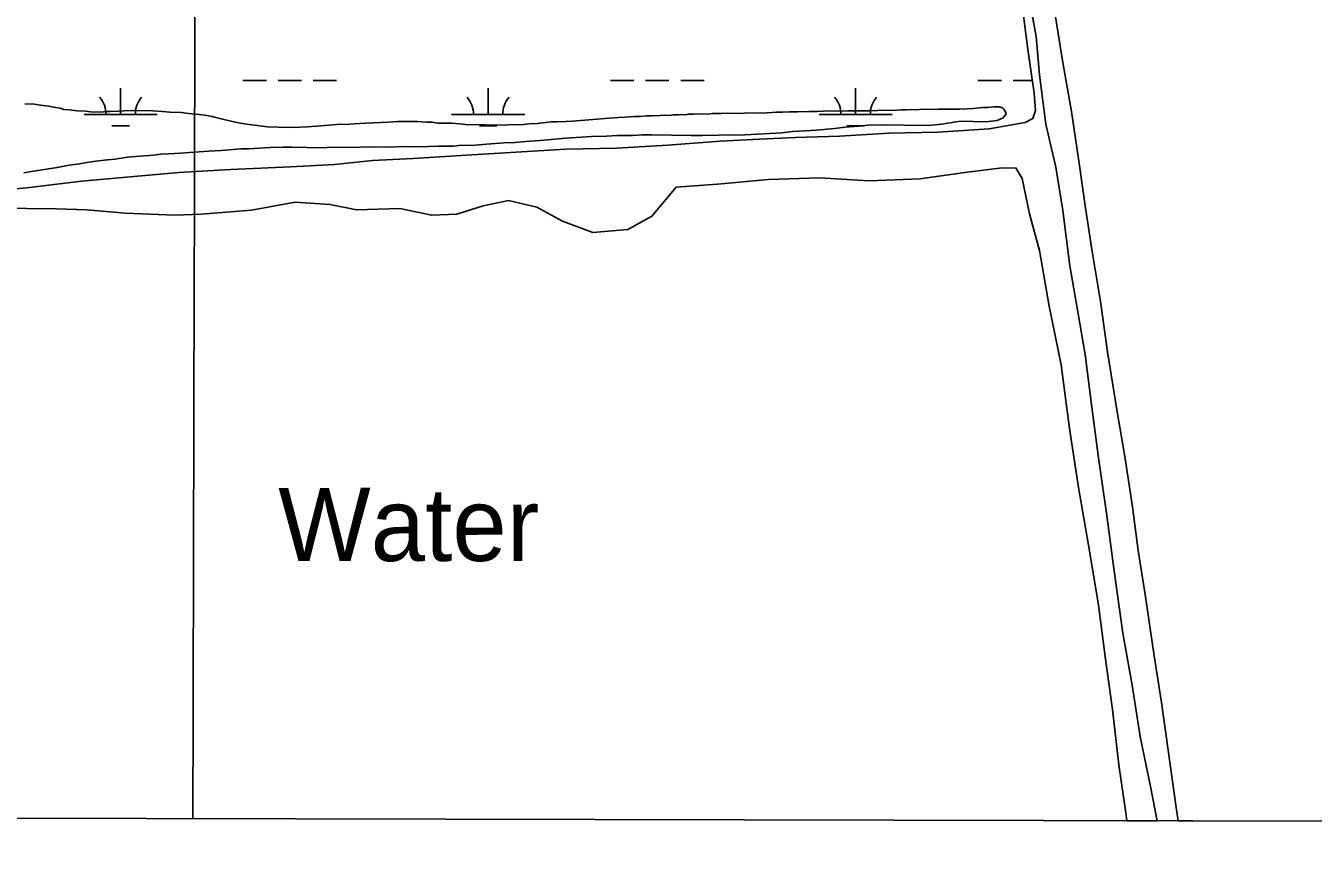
# Model space of a CAD drawing. Extents: x 3177185 to 3215018, y 812988 to 838321.
# Drawn here: x 3191596 to 3193354, y 818326 to 819458 of the extents above; entities that cross this region are included whole.
import ezdxf

# ---------------------------------------------------------------- set-up
doc = ezdxf.new("R2010")
doc.units = 0
for name, color, linetype in [('V-GRID-FRAM', 7, 'Continuous'), ('V-GRID-MAJR', 7, 'Continuous'), ('V-RIVR-IDEN', 7, 'Continuous'), ('V-SITE-VEGE', 7, 'Continuous'), ('V-TOPO-SHOR', 7, 'Continuous'), ('V-WETL-SWMP', 7, 'Continuous')]:
    doc.layers.add(name, color=color, linetype=linetype)

msp = doc.modelspace()

# ---------------------------------------------------------------- linework, layer by layer
at = {"layer": 'V-GRID-FRAM'}
msp.add_lwpolyline([(3181402.4, 836586.1), (3212801.6, 836513), (3212767.2, 818326.1), (3181352.2, 818399.3), (3181402.4, 836586.1)], dxfattribs=at)
at = {"layer": 'V-GRID-MAJR'}
msp.add_spline([(3191823.8, 818374.9), (3191838.8, 824434.1), (3191853.8, 830496.4), (3191868.8, 836558.7), (3191868.8, 836561.7)], degree=3, dxfattribs=at)
at = {"layer": 'V-SITE-VEGE'}
for p, q in [((3192964.9, 819500.9), (3192975.4, 819442.8)), ((3193011.9, 819407.5), (3193001.5, 819472.5)), ((3192975.4, 819442.8), (3192980.1, 819390.4)), ((3193024, 819340.5), (3193011.9, 819407.5)), ((3192980.1, 819390.4), (3192988.9, 819323.3)), ((3191607.5, 819350.5), (3191594.3, 819350.8)), ((3191615.3, 819349), (3191607.5, 819350.5)), ((3191627.1, 819347.9), (3191615.3, 819349)), ((3191633.5, 819346.4), (3191627.1, 819347.9)), ((3191642.6, 819344.9), (3191633.5, 819346.4)), ((3191647.6, 819343.4), (3191642.6, 819344.9)), ((3192880.4, 819344.4), (3192870.8, 819343.7)), ((3192889.5, 819344.7), (3192880.4, 819344.4)), ((3192902.3, 819345.9), (3192889.5, 819344.7)), ((3192909.6, 819346.2), (3192902.3, 819345.9)), ((3192917.9, 819347), (3192909.6, 819346.2)), ((3192925.2, 819346.8), (3192917.9, 819347)), ((3192929.7, 819345.4), (3192925.2, 819346.8)), ((3192931.5, 819343.5), (3192929.7, 819345.4)), ((3191654.9, 819342.9), (3191647.6, 819343.4)), ((3191665.8, 819341.3), (3191654.9, 819342.9)), ((3191677.2, 819341.1), (3191665.8, 819341.3)), ((3191684.5, 819340), (3191677.2, 819341.1)), ((3191698.6, 819339.8), (3191684.5, 819340)), ((3191705, 819340.6), (3191698.6, 819339.8)), ((3191711.4, 819340.5), (3191705, 819340.6)), ((3191721.9, 819340.8), (3191711.4, 819340.5)), ((3191729.7, 819341.5), (3191721.9, 819340.8)), ((3191740.7, 819341.8), (3191729.7, 819341.5)), ((3191769, 819341.3), (3191740.7, 819341.8)), ((3191782.6, 819340.6), (3191769, 819341.3)), ((3191792.2, 819339.5), (3191782.6, 819340.6)), ((3191808.2, 819339.2), (3191792.2, 819339.5)), ((3191817.7, 819337.7), (3191808.2, 819339.2)), ((3191832.3, 819336.5), (3191817.7, 819337.7)), ((3191840, 819335.5), (3191832.3, 819336.5)), ((3191850.1, 819333.5), (3191840, 819335.5)), ((3191853.2, 819333), (3191850.1, 819333.5)), ((3191864.1, 819330), (3191853.2, 819333)), ((3191871.9, 819328.1), (3191864.1, 819330)), ((3191886, 819325.1), (3191871.9, 819328.1)), ((3192112.8, 819327), (3192103.7, 819326.7)), ((3192130.6, 819326.7), (3192112.8, 819327)), ((3192342.4, 819327.5), (3192333.3, 819326.7)), ((3192392.2, 819331.2), (3192342.4, 819327.5)), ((3192405, 819332.3), (3192392.2, 819331.2)), ((3192414.2, 819332.6), (3192405, 819332.3)), ((3192427, 819333.8), (3192414.2, 819332.6)), ((3192434.7, 819333.6), (3192427, 819333.8)), ((3192443.4, 819334.8), (3192434.7, 819333.6)), ((3192451.2, 819334.7), (3192443.4, 819334.8)), ((3192462.1, 819335), (3192451.2, 819334.7)), ((3192467.6, 819335.3), (3192462.1, 819335)), ((3192475.4, 819335.2), (3192467.6, 819335.3)), ((3192480, 819336), (3192475.4, 819335.2)), ((3192487.3, 819335.9), (3192480, 819336)), ((3192491.8, 819336.3), (3192487.3, 819335.9)), ((3192496.9, 819336.2), (3192491.8, 819336.3)), ((3192500.1, 819337), (3192496.9, 819336.2)), ((3192507.4, 819336.9), (3192500.1, 819337)), ((3192513.8, 819337.2), (3192507.4, 819336.9)), ((3192527.4, 819337), (3192513.8, 819337.2)), ((3192532.9, 819337.8), (3192527.4, 819337)), ((3192540.7, 819337.7), (3192532.9, 819337.8)), ((3192545.3, 819338), (3192540.7, 819337.7)), ((3192553.5, 819338.4), (3192545.3, 819338)), ((3192573.6, 819338), (3192553.5, 819338.4)), ((3192580.9, 819338.8), (3192573.6, 819338)), ((3192601.4, 819338.4), (3192580.9, 819338.8)), ((3192621.1, 819339.4), (3192601.4, 819338.4)), ((3192629.3, 819339.8), (3192621.1, 819339.4)), ((3192638.9, 819340), (3192629.3, 819339.8)), ((3192649.4, 819339.9), (3192638.9, 819340)), ((3192665.3, 819340.5), (3192649.4, 819339.9)), ((3192676.3, 819340.7), (3192665.3, 819340.5)), ((3192692.7, 819341.4), (3192676.3, 819340.7)), ((3192703.7, 819341.2), (3192692.7, 819341.4)), ((3192719.2, 819341.4), (3192703.7, 819341.2)), ((3192730.2, 819341.6), (3192719.2, 819341.4)), ((3192747.5, 819341.3), (3192730.2, 819341.6)), ((3192758.9, 819342), (3192747.5, 819341.3)), ((3192773.1, 819342.2), (3192758.9, 819342)), ((3192780.4, 819342.1), (3192773.1, 819342.2)), ((3192790.9, 819342.8), (3192780.4, 819342.1)), ((3192797.8, 819342.7), (3192790.9, 819342.8)), ((3192804.1, 819343.1), (3192797.8, 819342.7)), ((3192811.4, 819342.9), (3192804.1, 819343.1)), ((3192821.5, 819343.7), (3192811.4, 819342.9)), ((3192836.6, 819343.4), (3192821.5, 819343.7)), ((3192841.6, 819343.8), (3192836.6, 819343.4)), ((3192853.9, 819343.5), (3192841.6, 819343.8)), ((3192870.8, 819343.7), (3192853.9, 819343.5)), ((3192866.4, 819326.4), (3192872.3, 819327.2)), ((3192872.3, 819327.2), (3192906.6, 819326.6)), ((3192906.6, 819326.6), (3192922.1, 819328.2)), ((3192922.1, 819328.2), (3192930.4, 819331.7)), ((3192930.4, 819331.7), (3192934.6, 819337.5)), ((3192933.7, 819340.3), (3192931.5, 819343.5)), ((3192934.6, 819337.5), (3192933.7, 819340.3)), ((3193034.9, 819267), (3193024, 819340.5)), ((3191896.9, 819323.1), (3191886, 819325.1)), ((3191915.1, 819320.9), (3191896.9, 819323.1)), ((3191926, 819319.8), (3191915.1, 819320.9)), ((3191940.2, 819319.1), (3191926, 819319.8)), ((3191957.5, 819318.8), (3191940.2, 819319.1)), ((3191969.8, 819319), (3191957.5, 819318.8)), ((3191979.4, 819319.8), (3191969.8, 819319)), ((3191993.1, 819320.4), (3191979.4, 819319.8)), ((3192015.1, 819322.3), (3191993.1, 819320.4)), ((3192025.6, 819323.1), (3192015.1, 819322.3)), ((3192030.6, 819323), (3192025.6, 819323.1)), ((3192052.1, 819324), (3192030.6, 819323)), ((3192059.9, 819324.7), (3192052.1, 819324)), ((3192090.9, 819326), (3192059.9, 819324.7)), ((3192103.7, 819326.7), (3192090.9, 819326)), ((3192142.5, 819326), (3192130.6, 819326.7)), ((3192150.7, 819325.9), (3192142.5, 819326)), ((3192158.4, 819324.8), (3192150.7, 819325.9)), ((3192177.6, 819324.5), (3192158.4, 819324.8)), ((3192188.1, 819323.8), (3192177.6, 819324.5)), ((3192196.3, 819322.8), (3192188.1, 819323.8)), ((3192250.1, 819321.8), (3192196.3, 819322.8)), ((3192260.2, 819322.6), (3192250.1, 819321.8)), ((3192267.9, 819322.4), (3192260.2, 819322.6)), ((3192275.7, 819322.7), (3192267.9, 819322.4)), ((3192283, 819323.5), (3192275.7, 819322.7)), ((3192294.4, 819324.2), (3192283, 819323.5)), ((3192313.2, 819326.2), (3192294.4, 819324.2)), ((3192321, 819326.5), (3192313.2, 819326.2)), ((3192333.3, 819326.7), (3192321, 819326.5)), ((3192569.4, 819308.4), (3192628.3, 819311.5)), ((3192628.3, 819311.5), (3192643, 819313)), ((3192643, 819313), (3192667.6, 819314.4)), ((3192667.6, 819314.4), (3192675.4, 819315.2)), ((3192675.4, 819315.2), (3192700.1, 819317.1)), ((3192700.1, 819317.1), (3192714.7, 819319.1)), ((3192714.7, 819319.1), (3192733.5, 819320.6)), ((3192733.5, 819320.6), (3192745.8, 819321.7)), ((3192745.8, 819321.7), (3192762.7, 819322.3)), ((3192762.7, 819322.3), (3192827.9, 819321.2)), ((3192827.9, 819321.2), (3192846.7, 819323.1)), ((3192846.7, 819323.1), (3192866.4, 819326.4)), ((3192988.9, 819323.3), (3193002.4, 819264.3)), ((3191947, 819291.6), (3191958.4, 819291.8)), ((3191958.4, 819291.8), (3192000.4, 819291.1)), ((3192000.4, 819291.1), (3192014.1, 819291.8)), ((3192014.1, 819291.8), (3192034.2, 819291.4)), ((3192034.2, 819291.4), (3192071.1, 819292.1)), ((3192071.1, 819292.1), (3192092.1, 819291.8)), ((3192092.1, 819291.8), (3192112.2, 819292.8)), ((3192112.2, 819292.8), (3192125.5, 819292.5)), ((3192125.5, 819292.5), (3192145.5, 819292.6)), ((3192145.5, 819292.6), (3192159.3, 819293.3)), ((3192159.3, 819293.3), (3192180.2, 819293.4)), ((3192180.2, 819293.4), (3192187.1, 819294.2)), ((3192187.1, 819294.2), (3192209.5, 819294.7)), ((3192209.5, 819294.7), (3192225, 819295.8)), ((3192225, 819295.8), (3192248.8, 819297.7)), ((3192248.8, 819297.7), (3192263.4, 819298.3)), ((3192263.4, 819298.3), (3192284.4, 819300.2)), ((3192284.4, 819300.2), (3192298.1, 819300.9)), ((3192298.1, 819300.9), (3192332.9, 819303.9)), ((3192332.9, 819303.9), (3192354.4, 819305.4)), ((3192354.4, 819305.4), (3192368.1, 819306.5)), ((3192368.1, 819306.5), (3192388.6, 819307)), ((3192388.6, 819307), (3192402.8, 819307.7)), ((3192402.8, 819307.7), (3192424.2, 819307.8)), ((3192424.2, 819307.8), (3192437.5, 819308.5)), ((3192437.5, 819308.5), (3192450.7, 819308.7)), ((3192450.7, 819308.7), (3192504.6, 819307.7)), ((3192504.6, 819307.7), (3192519.6, 819307.9)), ((3192519.6, 819307.9), (3192542, 819308.4)), ((3192542, 819308.4), (3192556.6, 819308.6)), ((3192556.6, 819308.6), (3192569.4, 819308.4)), ((3191691.5, 819272.8), (3191707.1, 819274.4)), ((3191707.1, 819274.4), (3191717.6, 819275.6)), ((3191717.6, 819275.6), (3191734.5, 819278)), ((3191734.5, 819278), (3191745.5, 819279.2)), ((3191745.5, 819279.2), (3191770.6, 819281)), ((3191770.6, 819281), (3191780.2, 819282.2)), ((3191780.2, 819282.2), (3191790.7, 819282.9)), ((3191790.7, 819282.9), (3191807.6, 819283.6)), ((3191807.6, 819283.6), (3191819.1, 819284.7)), ((3191819.1, 819284.7), (3191845.6, 819286.5)), ((3191845.6, 819286.5), (3191862.5, 819287.1)), ((3191862.5, 819287.1), (3191873.4, 819288.3)), ((3191873.4, 819288.3), (3191889.4, 819289.4)), ((3191889.4, 819289.4), (3191900.4, 819289.7)), ((3191900.4, 819289.7), (3191929.6, 819291.4)), ((3191929.6, 819291.4), (3191947, 819291.6)), ((3191593.1, 819256.8), (3191603.6, 819258.4)), ((3191603.6, 819258.4), (3191638.4, 819264.2)), ((3191638.4, 819264.2), (3191654.9, 819267.1)), ((3191654.9, 819267.1), (3191666.3, 819268.7)), ((3191666.3, 819268.7), (3191681.9, 819271.2)), ((3191681.9, 819271.2), (3191691.5, 819272.8)), ((3192878.1, 819257), (3192817.2, 819248.6)), ((3192925.3, 819263.2), (3192878.1, 819257)), ((3192947.6, 819263.4), (3192925.3, 819263.2)), ((3192956.3, 819249), (3192947.6, 819263.4)), ((3193002.4, 819264.3), (3193012.1, 819205.1)), ((3193042.5, 819211.9), (3193034.9, 819267)), ((3192540.2, 819241.1), (3192483.8, 819237.1)), ((3192609.8, 819247.7), (3192540.2, 819241.1)), ((3192680.2, 819250), (3192609.8, 819247.7)), ((3192746.9, 819246), (3192680.2, 819250)), ((3192817.2, 819248.6), (3192746.9, 819246)), ((3192966.6, 819200.9), (3192956.3, 819249)), ((3192483.8, 819237.1), (3192450.8, 819197.4)), ((3191637.4, 819207.5), (3191556.1, 819208.4)), ((3191679.1, 819206.4), (3191637.4, 819207.5)), ((3191731.8, 819201.6), (3191679.1, 819206.4)), ((3191904.1, 819206), (3191835.4, 819200.1)), ((3191963.6, 819216.8), (3191904.1, 819206)), ((3192010.8, 819213.5), (3191963.6, 819216.8)), ((3192047.6, 819206.1), (3192010.8, 819213.5)), ((3192106.6, 819207.9), (3192047.6, 819206.1)), ((3192150.2, 819198.8), (3192106.6, 819207.9)), ((3192220.1, 819211.9), (3192184.5, 819200.3)), ((3192255, 819218.8), (3192220.1, 819211.9)), ((3192293.8, 819209.9), (3192255, 819218.8)), ((3192328.8, 819190.8), (3192293.8, 819209.9)), ((3193012.1, 819205.1), (3193021.7, 819129.8)), ((3193052.1, 819149.2), (3193042.5, 819211.9)), ((3191798.9, 819199), (3191731.8, 819201.6)), ((3191835.4, 819200.1), (3191798.9, 819199)), ((3192184.5, 819200.3), (3192150.2, 819198.8)), ((3192370.3, 819175.5), (3192328.8, 819190.8)), ((3192450.8, 819197.4), (3192417.8, 819179.5)), ((3192980.3, 819150.5), (3192966.6, 819200.9)), ((3192417.8, 819179.5), (3192370.3, 819175.5)), ((3192993.2, 819074.8), (3192980.3, 819150.5)), ((3193063.4, 819081.1), (3193052.1, 819149.2)), ((3193021.7, 819129.8), (3193032.9, 819064.3)), ((3193073.2, 819012.1), (3193063.4, 819081.1)), ((3193009.5, 818994.4), (3192993.2, 819074.8)), ((3193032.9, 819064.3), (3193042.5, 819008.6)), ((3193086.1, 818930.4), (3193073.2, 819012.1)), ((3193021.3, 818907.5), (3193009.5, 818994.4)), ((3193042.5, 819008.6), (3193051.8, 818936.7)), ((3193051.8, 818936.7), (3193060.9, 818867.5)), ((3193096.5, 818869.2), (3193086.1, 818930.4)), ((3193033.5, 818826.9), (3193021.3, 818907.5)), ((3193060.9, 818867.5), (3193071.6, 818791.8)), ((3193107.3, 818800.6), (3193096.5, 818869.2)), ((3193048.7, 818737.7), (3193033.5, 818826.9)), ((3193115, 818741.2), (3193107.3, 818800.6)), ((3193071.6, 818791.8), (3193081.6, 818716.5)), ((3193060.7, 818666.4), (3193048.7, 818737.7)), ((3193124.4, 818681.1), (3193115, 818741.2)), ((3193081.6, 818716.5), (3193093.7, 818628.2)), ((3193136.9, 818596.9), (3193124.4, 818681.1)), ((3193070.4, 818592.6), (3193060.7, 818666.4)), ((3193093.7, 818628.2), (3193106.8, 818557.2)), ((3193079.9, 818523.9), (3193070.4, 818592.6)), ((3193146.7, 818533.2), (3193136.9, 818596.9)), ((3193106.8, 818557.2), (3193117.7, 818486.8)), ((3193088.3, 818448.4), (3193079.9, 818523.9)), ((3193166.9, 818389.9), (3193146.7, 818533.2)), ((3193117.7, 818486.8), (3193131.9, 818418.6)), ((3193097.8, 818382.5), (3193088.3, 818448.4)), ((3193131.9, 818418.6), (3193140.9, 818371.8)), ((3193099.4, 818371.9), (3193097.8, 818382.5)), ((3193169.7, 818371.8), (3193166.9, 818389.9)), ((3193140.9, 818371.8), (3193099.4, 818371.9)), ((3195083.3, 818367.3), (3193169.7, 818371.8))]:
    msp.add_line(p, q, dxfattribs=at)
at = {"layer": 'V-TOPO-SHOR'}
for points in [[(3192918.8, 819820.7), (3192925.8, 819765.7), (3192936.7, 819692.7), (3192947.4, 819617.7), (3192955.2, 819562.7), (3192964.9, 819500.9), (3192975.4, 819442.8), (3192980.1, 819390.4), (3192988.9, 819323.3), (3193002.4, 819264.3), (3193012.1, 819205.1), (3193021.7, 819129.8), (3193032.9, 819064.3), (3193042.5, 819008.6), (3193051.8, 818936.7), (3193060.9, 818867.5), (3193071.6, 818791.8), (3193081.6, 818716.5), (3193093.7, 818628.2), (3193106.8, 818557.2), (3193117.7, 818486.8), (3193131.9, 818418.6), (3193140.9, 818371.8)], [(3193001.5, 819472.5), (3193011.9, 819407.5), (3193024, 819340.5), (3193034.9, 819267), (3193042.5, 819211.9), (3193052.1, 819149.2), (3193063.4, 819081.1), (3193073.2, 819012.1), (3193086.1, 818930.4), (3193096.5, 818869.2), (3193107.3, 818800.6), (3193115, 818741.2), (3193124.4, 818681.1), (3193136.9, 818596.9), (3193146.7, 818533.2), (3193166.9, 818389.9), (3193169.7, 818371.8)], [(3191556.1, 819208.4), (3191637.4, 819207.5), (3191679.1, 819206.4), (3191731.8, 819201.6), (3191798.9, 819199), (3191835.4, 819200.1), (3191904.1, 819206), (3191963.6, 819216.8), (3192010.8, 819213.5), (3192047.6, 819206.1), (3192106.6, 819207.9), (3192150.2, 819198.8), (3192184.5, 819200.3), (3192220.1, 819211.9), (3192255, 819218.8), (3192293.8, 819209.9), (3192328.8, 819190.8), (3192370.3, 819175.5), (3192417.8, 819179.5), (3192450.8, 819197.4), (3192483.8, 819237.1), (3192540.2, 819241.1), (3192609.8, 819247.7), (3192680.2, 819250), (3192746.9, 819246), (3192817.2, 819248.6), (3192878.1, 819257), (3192925.3, 819263.2), (3192947.6, 819263.4), (3192956.3, 819249), (3192966.6, 819200.9), (3192980.3, 819150.5), (3192993.2, 819074.8), (3193009.5, 818994.4), (3193021.3, 818907.5), (3193033.5, 818826.9), (3193048.7, 818737.7), (3193060.7, 818666.4), (3193070.4, 818592.6), (3193079.9, 818523.9), (3193088.3, 818448.4), (3193097.8, 818382.5), (3193099.4, 818371.9)]]:
    msp.add_lwpolyline(points, dxfattribs=at)
at = {"layer": 'V-WETL-SWMP'}
for p, q in [((3191892.2, 819383), (3191924.2, 819383)), ((3191940.2, 819383), (3191972.2, 819383)), ((3191988.2, 819383), (3192020.2, 819383)), ((3192394.1, 819383), (3192426.1, 819383)), ((3192442.1, 819383), (3192474.1, 819383)), ((3192490.1, 819383), (3192522.1, 819383)), ((3192896, 819383), (3192928, 819383)), ((3192944, 819383), (3192970.1, 819383)), ((3191725.2, 819336.6), (3191725.2, 819372.6)), ((3192227.1, 819336.6), (3192227.1, 819372.6)), ((3192729, 819336.6), (3192729, 819372.6)), ((3191675.2, 819336.6), (3191775.2, 819336.6)), ((3192177.1, 819336.6), (3192277.1, 819336.6)), ((3192679, 819336.6), (3192779, 819336.6)), ((3191713.2, 819321.1), (3191737.2, 819321.1)), ((3192215.1, 819321.1), (3192239.1, 819321.1)), ((3192717, 819321.1), (3192741, 819321.1))]:
    msp.add_line(p, q, dxfattribs=at)
for points in [[(3192955.3, 819492.9), (3192964, 819425), (3192972.6, 819365.5), (3192974.6, 819341.8), (3192970.9, 819330.9), (3192960.7, 819325.6), (3192911.5, 819316.8), (3192841.6, 819312.3), (3192774.2, 819311), (3192706.9, 819306.9), (3192647, 819304.8), (3192597.5, 819302.8), (3192543.8, 819300.2), (3192472.6, 819294.7), (3192402.2, 819290.4), (3192333.3, 819289.1), (3192205, 819281.3), (3192124.5, 819276.3), (3192069.1, 819273.7), (3192017.5, 819268.3), (3191957.3, 819264.9)], [(3191957.3, 819264.9), (3191875.9, 819261.1), (3191804.9, 819257.1), (3191671.6, 819245.4), (3191596.9, 819236.3)], [(3191596.9, 819236.3), (3191513.5, 819229)]]:
    msp.add_lwpolyline(points, dxfattribs=at)
for centre, start, end in [((3191669.9, 819337), 359.2282, 40.7718), ((3191780.4, 819337), 139.2282, 180.7718), ((3192171.8, 819337), 359.2282, 40.7718), ((3192282.3, 819337), 139.2282, 180.7718), ((3192673.7, 819337), 359.2282, 40.7718), ((3192784.2, 819337), 139.2282, 180.7718)]:
    msp.add_arc(centre, 35.2, start, end, dxfattribs=at)

# ---------------------------------------------------------------- texts
at = {"layer": 'V-RIVR-IDEN'}
msp.add_text('Water', height=100, rotation=0.0375, dxfattribs=at).set_placement((3191940.5, 818726.5))

doc.saveas('drawing.dxf')
